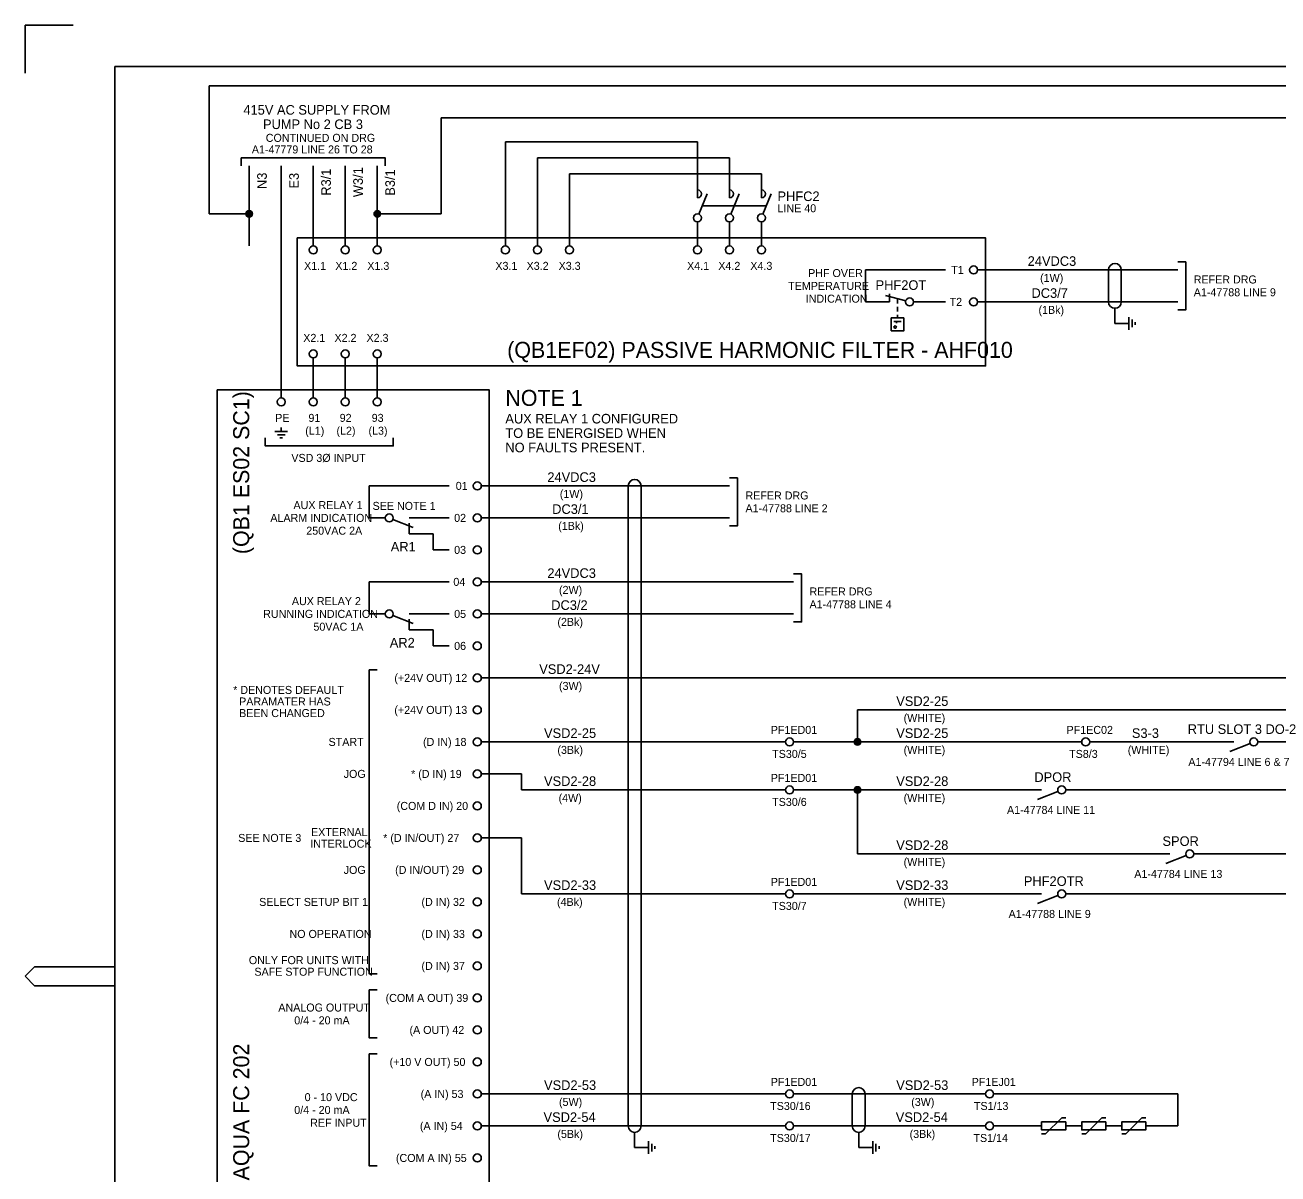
# Model space of a CAD drawing. Extents: x 0 to 841, y 0 to 594.
# Drawn here: x 0 to 391.3, y 235 to 594 of the extents above; entities that cross this region are included whole.
import ezdxf

# ---------------------------------------------------------------- set-up
doc = ezdxf.new("R2010")
doc.units = 0
for name, color, linetype in [('A1BORDER', 7, 'Continuous'), ('BASE', 7, 'Continuous'), ('Level 1', 7, 'Continuous'), ('Level 10', 7, 'Continuous'), ('Level 4', 7, 'Continuous'), ('Level 5', 7, 'Continuous'), ('Level 6', 7, 'Continuous')]:
    doc.layers.add(name, color=color, linetype=linetype)

msp = doc.modelspace()

# ---------------------------------------------------------------- linework, layer by layer
at = {"layer": 'A1BORDER'}
for p, q in [((0, 594), (15, 594)), ((0, 579), (0, 594)), ((28, 581), (829, 581)), ((28, 581), (28, 15)), ((3, 299.76), (0, 296.76)), ((28, 299.76), (3, 299.76)), ((3, 293.76), (0, 296.76)), ((28, 293.76), (3, 293.76))]:
    msp.add_line(p, q, dxfattribs=at)
at = {"layer": 'BASE'}
for p, q in [((338.37, 517.5), (338.37, 507.5)), ((342.37, 517.5), (342.37, 507.5)), ((340.37, 505.5), (340.37, 500.75)), ((344.74, 500.75), (340.37, 500.75)), ((188.37, 450), (188.37, 250)), ((192.37, 450), (192.37, 250)), ((258.37, 260), (258.37, 250)), ((262.37, 260), (262.37, 250)), ((190.37, 248), (190.37, 243.25)), ((260.37, 248), (260.37, 243.25)), ((194.74, 243.25), (190.37, 243.25)), ((264.74, 243.25), (260.37, 243.25))]:
    msp.add_line(p, q, dxfattribs=at)
for centre, start, end in [((340.37, 517.5), 0, 180), ((340.37, 507.5), 180, 0), ((190.37, 450), 0, 180), ((260.37, 260), 0, 180), ((190.37, 250), 180, 0), ((260.37, 250), 180, 0)]:
    msp.add_arc(centre, 2, start, end, dxfattribs=at)
at = {"layer": 'Level 1'}
for p, q in [((57.51, 535), (57.5, 575)), ((57.5, 575), (700, 575)), ((130, 535), (130, 565)), ((130, 565), (430, 565)), ((150, 557.5), (150, 525)), ((150, 557.5), (210, 557.5)), ((160, 552.5), (160, 525)), ((160, 552.5), (220, 552.5)), ((90, 550), (90, 525)), ((100, 550), (100, 525)), ((110, 525), (110, 550)), ((170, 525), (170, 547.5)), ((170, 547.5), (230, 547.5)), ((210, 540), (210, 542.5)), ((210.46, 534.91), (213, 541.25)), ((220, 540), (220, 542.5)), ((220.46, 534.91), (223, 541.25)), ((230, 540), (230, 542.5)), ((230.46, 534.91), (233, 541.25)), ((211.5, 537.5), (231.5, 537.5)), ((70, 535), (57.51, 535)), ((110, 535), (130, 535)), ((210, 532.5), (210, 525)), ((220, 532.5), (220, 525)), ((230, 525), (230, 532.5)), ((262.5, 517.5), (262.5, 507.5)), ((287.5, 517.5), (262.5, 517.5)), ((262.5, 507.5), (267.5, 507.5)), ((270, 507.5), (267.5, 507.5)), ((267.5, 507.5), (267.5, 507.5)), ((272.5, 508.5), (272.5, 507)), ((272.5, 506), (272.5, 504.5)), ((277.5, 507.5), (287.5, 507.5)), ((277.5, 507.5), (277.5, 507.5)), ((272.5, 503.5), (272.5, 502.5)), ((90, 490), (90, 477.5)), ((100, 490), (100, 477.5)), ((110, 477.5), (110, 490)), ((80, 467), (80, 468.25)), ((132.5, 450), (107.5, 450)), ((107.5, 450), (107.5, 440)), ((107.5, 440), (112.5, 440)), ((112.5, 440), (112.5, 440)), ((122.5, 440), (122.5, 440)), ((122.5, 440), (132.5, 440)), ((122.5, 435), (127.5, 435)), ((127.5, 435), (127.5, 430)), ((127.5, 430), (132.5, 430)), ((132.5, 420), (107.5, 420)), ((107.5, 420), (107.5, 410)), ((107.5, 410), (112.5, 410)), ((112.5, 410), (112.5, 410)), ((122.5, 410), (122.5, 410)), ((122.5, 410), (132.5, 410)), ((122.5, 405), (127.5, 405)), ((127.5, 405), (127.5, 400)), ((127.5, 400), (132.5, 400)), ((260, 370), (260, 380)), ((375, 370), (332.5, 370)), ((377.5, 370), (375, 370)), ((375, 370), (375, 370)), ((427.5, 370), (385, 370)), ((385, 370), (385, 370)), ((142.5, 360), (155, 360)), ((155, 360), (155, 355)), ((260, 355), (260, 335)), ((317.5, 355), (315, 355)), ((142.5, 340), (155, 340)), ((155, 340), (155, 322.5)), ((357.5, 335), (355, 335)), ((315, 322.5), (240, 322.5)), ((317.5, 322.5), (315, 322.5)), ((600, 322.5), (325, 322.5)), ((300, 260), (240, 260)), ((360, 260), (302.5, 260)), ((360, 260), (360, 250)), ((318.75, 247.5), (323.75, 252.5)), ((323.75, 252.5), (325, 252.5)), ((331.25, 247.5), (336.25, 252.5)), ((336.25, 252.5), (337.5, 252.5)), ((343.75, 247.5), (348.75, 252.5)), ((348.75, 252.5), (350, 252.5)), ((300, 250), (240, 250)), ((317.5, 250), (302.5, 250)), ((318.75, 247.5), (317.5, 247.5)), ((325, 250), (330, 250)), ((331.25, 247.5), (330, 247.5)), ((337.5, 250), (342.5, 250)), ((343.75, 247.5), (342.5, 247.5)), ((350, 250), (360, 250))]:
    msp.add_line(p, q, dxfattribs=at)
for points in [[(67.5, 550), (67.5, 552.5), (112.5, 552.5), (112.5, 550)], [(360, 520), (362.5, 520), (362.5, 505), (360, 505)], [(271.37, 501.37), (273.63, 501.37)], [(272.12, 501.62), (272.12, 500.87)], [(272.12, 499.64), (272.08, 499.82), (271.94, 499.95), (271.74, 500.01), (271.56, 499.95), (271.43, 499.82), (271.37, 499.64), (271.43, 499.44), (271.56, 499.3), (271.74, 499.26), (271.94, 499.3), (272.08, 499.44), (272.12, 499.64)], [(75, 465), (75, 462.5), (115, 462.5), (115, 465)], [(220, 452.5), (222.5, 452.5), (222.5, 437.5), (220, 437.5)], [(240, 422.5), (242.5, 422.5), (242.5, 407.5), (240, 407.5)], [(110, 297.5), (107.5, 297.5), (107.5, 392.5), (110, 392.5)], [(110, 277.5), (107.5, 277.5), (107.5, 292.5), (110, 292.5)], [(110, 237.5), (107.5, 237.5), (107.5, 272.5), (110, 272.5)]]:
    msp.add_lwpolyline(points, dxfattribs=at)
for points in [[(85, 527.5), (300, 527.5), (300, 487.5), (85, 487.5)], [(274.5, 502.5), (274.5, 498.5), (270.5, 498.5), (270.5, 502.5)], [(60, 480), (145, 480), (145, 160), (60, 160)]]:
    msp.add_lwpolyline(points, close=True, dxfattribs=at)
for centre in [(210, 533.75), (220, 533.75), (230, 533.75)]:
    msp.add_circle(centre, 1.25, dxfattribs=at)
for centre in [(210, 541.25), (220, 541.25), (230, 541.25)]:
    msp.add_arc(centre, 1.25, 270, 90, dxfattribs=at)
at = {"layer": 'Level 10'}
for p, q in [((69, 535), (69, 535)), ((69.1, 534.56), (69.1, 535.44)), ((69.4, 534.2), (69.4, 535.8)), ((69.7, 534.05), (69.7, 535.95)), ((70, 534), (70, 535.99)), ((70.3, 534.05), (70.3, 535.95)), ((70.6, 534.2), (70.6, 535.8)), ((70.9, 534.56), (70.9, 535.44)), ((109, 535), (109, 535)), ((109.1, 534.56), (109.1, 535.44)), ((109.4, 534.2), (109.4, 535.8)), ((109.7, 534.05), (109.7, 535.95)), ((110, 534), (110, 535.99)), ((110.3, 534.05), (110.3, 535.95)), ((110.6, 534.2), (110.6, 535.8)), ((110.9, 534.56), (110.9, 535.44)), ((275.04, 507.82), (268.75, 509.5)), ((270, 510), (270, 507.5)), ((344.74, 498.75), (344.74, 502.75)), ((345.74, 499.55), (345.74, 501.95)), ((346.74, 500.35), (346.74, 501.15)), ((78, 467), (82, 467)), ((78.8, 466), (81.2, 466)), ((79.6, 465), (80.4, 465)), ((114.91, 439.54), (121.25, 437)), ((120, 440), (122.5, 440)), ((120, 438.37), (120, 435)), ((120, 435), (122.5, 435)), ((114.91, 409.54), (121.25, 407)), ((120, 410), (122.5, 410)), ((120, 408.37), (120, 405)), ((120, 405), (122.5, 405)), ((259, 370), (259, 370)), ((259.1, 369.56), (259.1, 370.44)), ((259.4, 369.2), (259.4, 370.8)), ((259.7, 369.05), (259.7, 370.95)), ((260, 369), (260, 370.99)), ((260.3, 369.05), (260.3, 370.95)), ((260.6, 369.2), (260.6, 370.8)), ((260.9, 369.56), (260.9, 370.44)), ((382.59, 369.54), (376.25, 367)), ((259, 355), (259, 355)), ((259.1, 354.56), (259.1, 355.44)), ((259.4, 354.2), (259.4, 355.8)), ((259.7, 354.05), (259.7, 355.95)), ((260, 354), (260, 355.99)), ((260.3, 354.05), (260.3, 355.95)), ((260.6, 354.2), (260.6, 355.8)), ((260.9, 354.56), (260.9, 355.44)), ((322.59, 354.54), (316.25, 352)), ((362.59, 334.54), (356.25, 332)), ((322.59, 322.04), (316.25, 319.5)), ((194.74, 241.25), (194.74, 245.25)), ((195.74, 242.05), (195.74, 244.45)), ((196.74, 242.85), (196.74, 243.65)), ((264.74, 241.25), (264.74, 245.25)), ((265.74, 242.05), (265.74, 244.45)), ((266.74, 242.85), (266.74, 243.65))]:
    msp.add_line(p, q, dxfattribs=at)
for points in [[(317.5, 250), (317.5, 248.75), (325, 248.75), (325, 251.25), (317.5, 251.25), (317.5, 250)], [(330, 250), (330, 248.75), (337.5, 248.75), (337.5, 251.25), (330, 251.25), (330, 250)], [(342.5, 250), (342.5, 248.75), (350, 248.75), (350, 251.25), (342.5, 251.25), (342.5, 250)]]:
    msp.add_lwpolyline(points, dxfattribs=at)
for centre, radius in [((70, 535), 1), ((110, 535), 1), ((276.25, 507.5), 1.25), ((113.75, 440), 1.25), ((113.75, 410), 1.25), ((260, 370), 1), ((383.75, 370), 1.25), ((323.75, 355), 1.25), ((260, 355), 1), ((363.75, 335), 1.25), ((323.75, 322.5), 1.25)]:
    msp.add_circle(centre, radius, dxfattribs=at)
at = {"layer": 'Level 4'}
for centre in [(90, 523.75), (100, 523.75), (110, 523.75), (150, 523.75), (160, 523.75), (170, 523.75), (210, 523.75), (220, 523.75), (230, 523.75), (90, 491.25), (100, 491.25), (110, 491.25), (80, 476.25), (90, 476.25), (100, 476.25), (110, 476.25)]:
    msp.add_circle(centre, 1.25, dxfattribs=at)
at = {"layer": 'Level 5'}
for p, q in [((210, 557.5), (210, 542.5)), ((220, 552.5), (220, 542.5)), ((70, 550), (70, 525)), ((80, 550), (80, 477.5)), ((230, 547.5), (230, 542.5))]:
    msp.add_line(p, q, dxfattribs=at)
for centre in [(296.25, 517.5), (296.25, 507.5), (141.25, 450), (141.25, 440), (141.25, 430), (141.25, 420), (141.25, 410), (141.25, 400), (141.25, 390), (141.25, 380), (141.25, 370), (238.75, 370), (331.25, 370), (141.25, 360), (238.75, 355), (141.25, 350), (141.25, 340), (141.25, 330), (141.25, 320), (238.75, 322.5), (141.25, 310), (141.25, 300), (141.25, 290), (141.25, 280), (141.25, 270), (141.25, 260), (238.75, 260), (301.25, 260), (141.25, 250), (238.75, 250), (301.25, 250), (141.25, 240)]:
    msp.add_circle(centre, 1.25, dxfattribs=at)
at = {"layer": 'Level 6'}
for p, q in [((297.5, 517.5), (360, 517.5)), ((297.5, 507.5), (360, 507.5)), ((142.5, 450), (220, 450)), ((142.5, 440), (220, 440)), ((142.5, 420), (240, 420)), ((142.5, 410), (240, 410)), ((142.5, 390), (601.25, 390)), ((260, 380), (520, 380)), ((142.5, 370), (237.5, 370)), ((240, 370), (330, 370)), ((155, 355), (237.5, 355)), ((240, 355), (315, 355)), ((325, 355), (435, 355)), ((260, 335), (355, 335)), ((365, 335), (420, 335)), ((155, 322.5), (237.5, 322.5)), ((142.5, 260), (237.5, 260)), ((142.5, 250), (237.5, 250))]:
    msp.add_line(p, q, dxfattribs=at)

# ---------------------------------------------------------------- texts
at = {"layer": 'Level 1'}
for s, height, p in [('CONTINUED ON DRG', 2.5, (75.18, 557.5)), ('A1-47779 LINE 26 TO 28', 2.5, (70.83, 553.88)), ('PHFC2', 3, (235, 539)), ('LINE 40', 2.5, (235, 535.5)), ('X1.1', 2.5, (87.14, 517.5)), ('X1.2', 2.5, (96.89, 517.5)), ('X1.3', 2.5, (106.89, 517.5)), ('X3.1', 2.5, (146.89, 517.5)), ('X3.2', 2.5, (156.64, 517.5)), ('X3.3', 2.5, (166.64, 517.5)), ('X4.1', 2.5, (206.76, 517.5)), ('X4.2', 2.5, (216.51, 517.5)), ('X4.3', 2.5, (226.51, 517.5)), ('PHF OVER', 2.5, (244.56, 515.25)), ('T1', 2.5, (289.26, 516.25)), ('TEMPERATURE', 2.5, (238.33, 511.25)), ('REFER DRG', 2.5, (365, 513.25)), ('INDICATION', 2.5, (243.81, 507.25)), ('T2', 2.5, (288.76, 506.25)), ('A1-47788 LINE 9', 2.5, (365, 509.25)), ('X2.1', 2.5, (86.89, 495)), ('X2.2', 2.5, (96.64, 495)), ('X2.3', 2.5, (106.64, 495)), ('(QB1EF02) PASSIVE HARMONIC FILTER - AHF010', 5, (150.58, 490)), ('NOTE 1', 5, (150, 475)), ('PE', 2.5, (78.13, 470)), ('91', 2.5, (88.5, 470)), ('92', 2.5, (98.26, 470)), ('93', 2.5, (108.26, 470)), ('AUX RELAY 1 CONFIGURED', 3, (150, 469.5)), ('(L1)', 2.5, (87.51, 465.99)), ('(L2)', 2.5, (97.26, 465.99)), ('(L3)', 2.5, (107.26, 465.99)), ('TO BE ENERGISED WHEN', 3, (150, 465)), ('NO FAULTS PRESENT.', 3, (150, 460.5)), ('VSD 3Ø INPUT', 2.5, (83.17, 457.5)), ('01', 2.5, (134.51, 448.75)), ('REFER DRG', 2.5, (225, 445.75)), ('AUX RELAY 1', 2.5, (83.83, 442.75)), ('SEE NOTE 1', 2.5, (108.54, 442.5)), ('A1-47788 LINE 2', 2.5, (225, 441.75)), ('ALARM INDICATION', 2.5, (76.61, 438.75)), ('02', 2.5, (134.01, 438.75)), ('250VAC 2A', 2.5, (87.82, 434.75)), ('03', 2.5, (134.01, 428.75)), ('04', 2.5, (133.76, 418.75)), ('AUX RELAY 2', 2.5, (83.33, 412.75)), ('REFER DRG', 2.5, (245, 415.75)), ('RUNNING INDICATION', 2.5, (74.37, 408.75)), ('05', 2.5, (134.01, 408.75)), ('A1-47788 LINE 4', 2.5, (245, 411.75)), ('50VAC 1A', 2.5, (90.06, 404.75)), ('06', 2.5, (134.01, 398.75)), ('(+24V OUT) 12', 2.5, (115.34, 388.75)), ('* DENOTES DEFAULT', 2.5, (65, 385)), ('  PARAMATER HAS', 2.5, (65, 381.38)), ('  BEEN CHANGED', 2.5, (65, 377.76)), ('(+24V OUT) 13', 2.5, (115.34, 378.75)), ('PF1ED01', 2.5, (232.9, 372.5)), ('PF1EC02', 2.5, (325.27, 372.5)), ('START', 2.5, (94.79, 368.75)), ('(D IN) 18', 2.5, (124.3, 368.75)), ('JOG', 2.5, (99.52, 358.75)), ('* (D IN) 19', 2.5, (120.56, 358.75)), ('PF1ED01', 2.5, (232.9, 357.5)), ('(COM D IN) 20', 2.5, (116.08, 348.75)), ('SEE NOTE 3', 2.5, (66.57, 338.75)), ('EXTERNAL', 2.5, (89.31, 340.56)), ('* (D IN/OUT) 27', 2.5, (111.85, 338.75)), ('INTERLOCK', 2.5, (89.07, 336.94)), ('JOG', 2.5, (99.52, 328.75)), ('(D IN/OUT) 29', 2.5, (115.58, 328.75)), ('PF1ED01', 2.5, (232.9, 325)), ('SELECT SETUP BIT 1', 2.5, (73.12, 318.75)), ('(D IN) 32', 2.5, (123.8, 318.75)), ('NO OPERATION', 2.5, (82.59, 308.75)), ('(D IN) 33', 2.5, (123.8, 308.75)), ('ONLY FOR UNITS WITH', 2.5, (69.89, 300.56)), ('(D IN) 37', 2.5, (123.8, 298.75)), ('SAFE STOP FUNCTION', 2.5, (71.63, 296.94)), ('(COM A OUT) 39', 2.5, (112.6, 288.75)), ('ANALOG OUTPUT', 2.5, (79.1, 285.75)), ('0/4 - 20 mA', 2.5, (84.08, 281.75)), ('(A OUT) 42', 2.5, (120.07, 278.75)), ('(+10 V OUT) 50', 2.5, (113.84, 268.75)), ('PF1ED01', 2.5, (232.9, 262.5)), ('PF1EJ01', 2.5, (295.65, 262.5)), ('0 - 10 VDC', 2.5, (87.32, 257.75)), ('(A IN) 53', 2.5, (123.55, 258.75)), ('0/4 - 20 mA', 2.5, (84.08, 253.75)), ('REF INPUT', 2.5, (89.06, 249.75)), ('(A IN) 54', 2.5, (123.31, 248.75)), ('(COM A IN) 55', 2.5, (115.83, 238.75))]:
    msp.add_text(s, height=height, dxfattribs=at).set_placement(p)
for s, height, p in [('R3/1', 3, (95.5, 540.67)), ('W3/1', 3, (105.5, 540.22)), ('B3/1', 3, (115.5, 540.67)), ('N3', 3, (75.5, 542.76)), ('E3', 3, (85.5, 542.91)), ('(QB1 ES02 SC1)', 5, (70, 428.68)), ('VSD - DANFOSS VLT AQUA FC 202', 5, (70, 165))]:
    msp.add_text(s, height=height, rotation=90, dxfattribs=at).set_placement(p)
at = {"layer": 'Level 5'}
for s, height, p in [('415V AC SUPPLY FROM', 3, (68.19, 566)), ('PUMP No 2 CB 3', 3, (74.31, 561.5)), ('24VDC3', 3, (313.13, 518.75)), ('PHF2OT', 3, (265.63, 511.25)), ('(1W)', 2.5, (317.01, 513.75)), ('DC3/7', 3, (314.32, 508.75)), ('(1Bk)', 2.5, (316.51, 503.75)), ('24VDC3', 3, (163.12, 451.25)), ('(1W)', 2.5, (167.01, 446.25)), ('DC3/1', 3, (164.63, 441.25)), ('(1Bk)', 2.5, (166.51, 436.25)), ('AR1', 3, (114.21, 429.5)), ('24VDC3', 3, (163.12, 421.25)), ('(2W)', 2.5, (166.76, 416.25)), ('DC3/2', 3, (164.33, 411.25)), ('(2Bk)', 2.5, (166.26, 406.25)), ('AR2', 3, (113.91, 399.5)), ('VSD2-24V', 3, (160.58, 391.25)), ('(3W)', 2.5, (166.76, 386.25)), ('VSD2-25', 3, (272.08, 381.25)), ('(WHITE)', 2.5, (274.39, 376.25)), ('VSD2-25', 3, (162.08, 371.25)), ('VSD2-25', 3, (272.08, 371.25)), ('S3-3', 3, (345.67, 371.25)), ('RTU SLOT 3 DO-2', 3, (363.12, 372.5)), ('(3Bk)', 2.5, (166.26, 366.25)), ('(WHITE)', 2.5, (274.39, 366.25)), ('(WHITE)', 2.5, (344.39, 366.25)), ('TS30/5', 2.5, (233.33, 365)), ('TS8/3', 2.5, (326.08, 365)), ('A1-47794 LINE 6 & 7', 2.5, (363.32, 362.5)), ('DPOR', 3, (315.22, 357.5)), ('VSD2-28', 3, (162.08, 356.25)), ('VSD2-28', 3, (272.08, 356.25)), ('(4W)', 2.5, (166.63, 351.25)), ('TS30/6', 2.5, (233.33, 350)), ('(WHITE)', 2.5, (274.39, 351.25)), ('A1-47784 LINE 11', 2.5, (306.68, 347.5)), ('SPOR', 3, (355.22, 337.5)), ('VSD2-28', 3, (272.08, 336.25)), ('(WHITE)', 2.5, (274.39, 331.25)), ('A1-47784 LINE 13', 2.5, (346.43, 327.5)), ('VSD2-33', 3, (162.08, 323.75)), ('VSD2-33', 3, (272.08, 323.75)), ('PHF2OTR', 3, (311.93, 325)), ('(4Bk)', 2.5, (166.14, 318.75)), ('(WHITE)', 2.5, (274.39, 318.75)), ('TS30/7', 2.5, (233.33, 317.5)), ('A1-47788 LINE 9', 2.5, (307.18, 315)), ('VSD2-53', 3, (162.08, 261.25)), ('VSD2-53', 3, (272.08, 261.25)), ('(5W)', 2.5, (166.76, 256.25)), ('(3W)', 2.5, (276.76, 256.25)), ('TS30/16', 2.5, (232.71, 255)), ('TS1/13', 2.5, (296.33, 255)), ('VSD2-54', 3, (161.93, 251.25)), ('VSD2-54', 3, (271.93, 251.25)), ('(5Bk)', 2.5, (166.26, 246.25)), ('TS30/17', 2.5, (232.71, 245)), ('(3Bk)', 2.5, (276.26, 246.25)), ('TS1/14', 2.5, (296.2, 245))]:
    msp.add_text(s, height=height, dxfattribs=at).set_placement(p)

doc.saveas('drawing.dxf')
